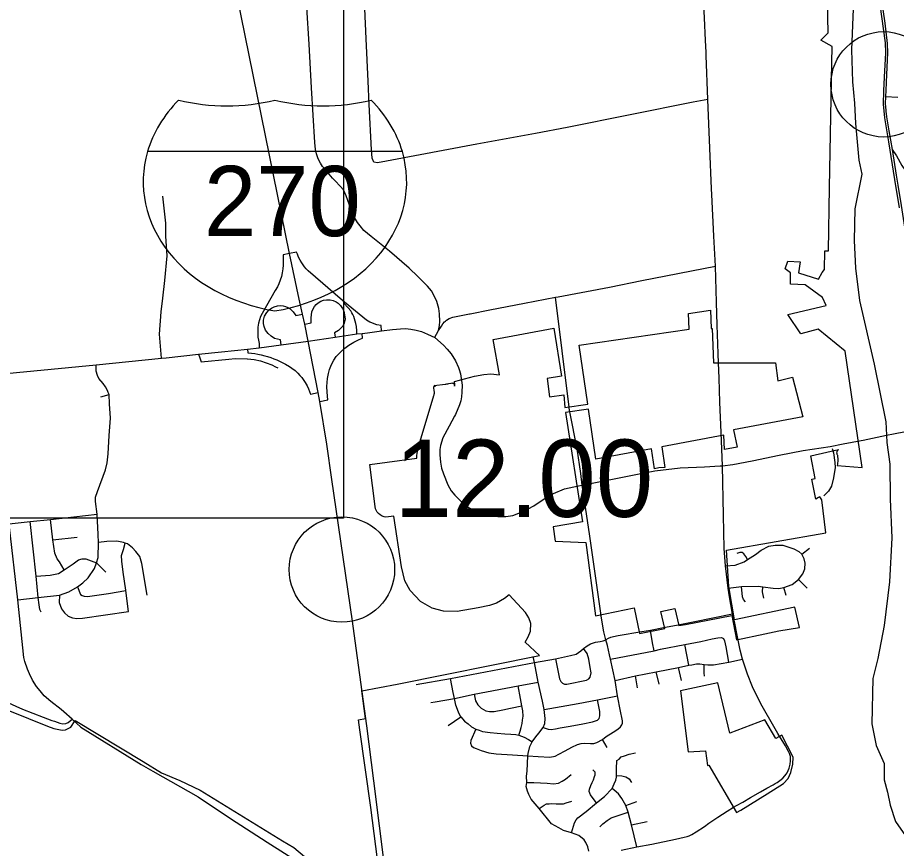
# Model space of a CAD drawing. Extents: x 1659811 to 1934326, y 644115 to 934867.
# Drawn here: x 1789672 to 1802180, y 733916 to 745742 of the extents above; entities that cross this region are included whole.
import ezdxf

# ---------------------------------------------------------------- set-up
doc = ezdxf.new("R2010")
doc.units = 0
for name, color, linetype in [('Default', 7, 'Continuous'), ('GM_X_City_Street', 7, 'Continuous'), ('GM_X_Corporation', 7, 'Continuous'), ('GM_X_County_Road', 7, 'Continuous'), ('GM_X_Interchange_Ramps', 7, 'Continuous'), ('GM_X_Interstate_Route', 7, 'Continuous'), ('GM_X_Interstate_Shield', 7, 'Continuous'), ('GM_X_Township', 7, 'Continuous'), ('GM_X_Township_Road', 7, 'Continuous'), ('GM_X_US_Route', 7, 'Continuous'), ('SC_Scratch1', 7, 'Continuous')]:
    doc.layers.add(name, color=color, linetype=linetype)

msp = doc.modelspace()

# ---------------------------------------------------------------- linework, layer by layer
at = {"layer": 'Default'}
for centre in [(1801998, 744792), (1794288, 737885)]:
    msp.add_circle(centre, 750, dxfattribs=at)
at = {"layer": 'GM_X_City_Street'}
for points in [[(1795663, 741290), (1795678, 741361), (1795683, 741414), (1795679, 741527), (1795668, 741602), (1795639, 741699), (1795602, 741783), (1795561, 741853), (1795507, 741919), (1795370, 742058), (1795243, 742175), (1794967, 742417), (1794706, 742627), (1794600, 742710), (1794548, 742777), (1794511, 742823), (1794469, 742896), (1794397, 743073), (1794350, 743203), (1794310, 743288), (1794261, 743343), (1794192, 743419), (1794155, 743455), (1794083, 743543), (1794013, 743621), (1793984, 743671), (1793952, 743733), (1793927, 743805), (1793912, 743865), (1793901, 743964), (1793856, 744742), (1793822, 745363), (1793790, 745884)], [(1799549, 743305), (1799525, 743884), (1799496, 744577), (1799472, 745204), (1799470, 745250)], [(1802022, 744618), (1802202, 744611)], [(1799496, 744577), (1799289, 744537)], [(1802119, 743863), (1802179, 743775), (1802258, 743638), (1802335, 743526), (1802389, 743466), (1802417, 743438), (1802451, 743403), (1802563, 743352), (1802790, 743282), (1802918, 743227)], [(1791719, 740894), (1791693, 741238), (1791715, 741554), (1791737, 741750), (1791769, 742000), (1791802, 742349), (1791780, 742632), (1791780, 742818), (1791737, 743199)], [(1795616, 741203), (1795636, 741236), (1795663, 741290), (1795705, 741352), (1795726, 741382), (1795748, 741410), (1795761, 741423)], [(1792575, 740984), (1792943, 741023), (1793111, 741042), (1793423, 741084), (1793807, 741137), (1794194, 741191), (1794500, 741239), (1794577, 741246), (1794650, 741255), (1794852, 741283), (1795006, 741303), (1795067, 741309), (1795123, 741314), (1795192, 741315), (1795267, 741308), (1795345, 741293), (1795422, 741272), (1795505, 741238), (1795608, 741189), (1795616, 741203)], [(1795608, 741189), (1795735, 741080), (1795787, 741024), (1795844, 740955), (1795905, 740857), (1795947, 740763), (1795955, 740734)], [(1791786, 740901), (1792249, 740949), (1792575, 740984)], [(1799686, 739836), (1799686, 739837), (1799668, 740268), (1799655, 740610), (1799648, 740830), (1799643, 740956), (1799637, 741097)], [(1785644, 740199), (1786132, 740262), (1786526, 740311), (1786898, 740356), (1787185, 740392), (1787465, 740426), (1788258, 740523), (1789260, 740650), (1790792, 740800), (1791719, 740894), (1791786, 740901)], [(1792249, 740949), (1792266, 740900), (1792287, 740842), (1792680, 740880), (1792769, 740889), (1792938, 740884)], [(1792938, 740884), (1792945, 740884), (1793040, 740874), (1793130, 740856), (1793290, 740797), (1793344, 740773), (1793376, 740755)], [(1789673, 737452), (1789966, 737487), (1790268, 737519), (1790402, 737566), (1790524, 737637), (1790600, 737694), (1790675, 737769), (1790766, 737899), (1790797, 737979), (1790821, 738059), (1790823, 738271), (1790819, 738382), (1790805, 738673), (1790781, 738852), (1790783, 738914), (1790811, 738998), (1790921, 739307), (1790947, 739405), (1790960, 739531), (1790977, 739792), (1790992, 740041), (1790981, 740243), (1790973, 740376), (1790962, 740406), (1790952, 740434), (1790924, 740487), (1790891, 740533), (1790830, 740607), (1790808, 740647), (1790790, 740710), (1790792, 740800)], [(1795955, 740734), (1795974, 740669), (1795997, 740511), (1795995, 740409), (1795989, 740343), (1795979, 740286), (1795963, 740232), (1795903, 740091), (1795892, 740070)], [(1790330, 735859), (1790292, 735892), (1790145, 736005), (1790050, 736089), (1789991, 736157), (1789940, 736221), (1789885, 736311), (1789842, 736402), (1789813, 736469), (1789773, 736577), (1789761, 736632), (1789673, 737452), (1789559, 738488), (1789553, 738537), (1789407, 739533), (1789344, 740018), (1789285, 740516), (1789260, 740650)], [(1790856, 740345), (1790973, 740376)], [(1797523, 740183), (1797520, 740200), (1797516, 740235)], [(1795892, 740070), (1795814, 739927), (1795724, 739761), (1795689, 739652), (1795682, 739594), (1795682, 739520), (1795691, 739416), (1795707, 739330), (1795733, 739250), (1795796, 739091), (1795843, 739007), (1795893, 738943), (1795951, 738888), (1796013, 738827), (1796101, 738765), (1796186, 738727), (1796328, 738676), (1796450, 738646), (1796505, 738641), (1796619, 738639), (1796722, 738657), (1796784, 738678), (1796916, 738736), (1796940, 738750)], [(1802139, 739816), (1802652, 739919)], [(1801677, 739723), (1801706, 739729), (1802039, 739796), (1802137, 739815), (1802139, 739816)], [(1801264, 739609), (1801286, 739547), (1801303, 739411), (1801309, 739337), (1801286, 739190), (1801258, 739072), (1801212, 739000), (1801146, 738935)], [(1783677, 739468), (1783922, 739315), (1784567, 738918), (1785211, 738522), (1786306, 737848), (1786531, 737713), (1787324, 737219), (1787916, 736848), (1788483, 736500), (1788730, 736352), (1788792, 736319), (1789122, 736169), (1789347, 736074), (1789742, 735899), (1790034, 735782), (1790159, 735738)], [(1796940, 738750), (1797017, 738793), (1797153, 738883), (1797265, 738949), (1797300, 738970), (1797458, 739032), (1797655, 739076), (1797706, 739086)], [(1789553, 738537), (1789852, 738568), (1790142, 738600), (1790805, 738673)], [(1790006, 737278), (1789990, 737318), (1789978, 737381), (1789966, 737487), (1789935, 737792), (1789852, 738568)], [(1790337, 737879), (1790270, 737993), (1790234, 738039), (1790201, 738117), (1790175, 738306), (1790142, 738600)], [(1790175, 738306), (1790522, 738348)], [(1791517, 737523), (1791441, 737970), (1791411, 738069), (1791353, 738143), (1791306, 738194), (1791238, 738250), (1791202, 738263), (1791180, 738270), (1791086, 738289), (1790940, 738283), (1790823, 738271)], [(1791252, 737289), (1791214, 737585), (1791213, 737592), (1791174, 737847), (1791157, 738004), (1791153, 738086), (1791178, 738170), (1791202, 738263)], [(1799747, 737936), (1799887, 737946), (1800011, 737994), (1800061, 738029), (1800172, 738101), (1800255, 738162), (1800366, 738216), (1800452, 738233), (1800563, 738231), (1800636, 738210), (1800722, 738178), (1800792, 738141), (1800833, 738105)], [(1799783, 737618), (1799973, 737646), (1800212, 737649), (1800280, 737640), (1800426, 737618), (1800508, 737615), (1800577, 737632), (1800694, 737673), (1800787, 737744), (1800849, 737826), (1800875, 737895), (1800881, 737978), (1800866, 738039), (1800833, 738105)], [(1800061, 738029), (1800035, 738072), (1800009, 738108), (1799982, 738127), (1799949, 738128), (1799910, 738112)], [(1800833, 738105), (1800943, 738188)], [(1789935, 737792), (1790134, 737806), (1790252, 737828), (1790337, 737879), (1790461, 737966), (1790539, 738023), (1790593, 738039), (1790644, 738040), (1790797, 737979)], [(1790797, 737979), (1790930, 737850)], [(1800787, 737744), (1800911, 737622)], [(1790524, 737637), (1790565, 737530), (1790593, 737514), (1790621, 737506), (1790669, 737504), (1790967, 737543), (1791214, 737585)], [(1800031, 737424), (1800004, 737458), (1799991, 737499), (1799973, 737646)], [(1800295, 737478), (1800274, 737569), (1800280, 737640)], [(1800612, 737516), (1800577, 737632)], [(1790268, 737519), (1790264, 737417), (1790298, 737325), (1790338, 737269), (1790394, 737224), (1790455, 737200), (1790517, 737190), (1790595, 737193), (1791252, 737289)], [(1798045, 736887), (1798016, 736998), (1797975, 737251)], [(1798557, 736998), (1798218, 736940), (1798110, 736918), (1798075, 736905), (1798045, 736887)], [(1798733, 736729), (1798709, 736844), (1798679, 737019)], [(1799073, 737095), (1799048, 737091), (1798867, 737055)], [(1797031, 736564), (1797328, 736616), (1797540, 736660), (1797624, 736681), (1797687, 736727), (1797724, 736760), (1797778, 736801), (1797827, 736830), (1797895, 736851), (1797962, 736862), (1798006, 736873), (1798045, 736887)], [(1798252, 735645), (1798270, 735675), (1798279, 735699), (1798282, 735732), (1798277, 735755), (1798254, 735869), (1798211, 736086), (1798177, 736306), (1798112, 736612), (1798095, 736673), (1798069, 736806), (1798045, 736887)], [(1798112, 736612), (1798733, 736729), (1798823, 736751), (1799170, 736818), (1799398, 736861), (1799557, 736899), (1799638, 736911), (1799690, 736917), (1799717, 736902)], [(1799795, 736566), (1799758, 736787), (1799748, 736827), (1799740, 736870), (1799717, 736902)], [(1800494, 735551), (1800455, 735618), (1800249, 735973), (1800132, 736217), (1800061, 736396), (1799991, 736610), (1799957, 736739), (1799918, 736926), (1799912, 736953)], [(1797328, 736616), (1797362, 736447), (1797383, 736332), (1797403, 736292), (1797425, 736269), (1797454, 736253), (1797487, 736252), (1797770, 736310), (1797803, 736329), (1797823, 736353), (1797836, 736414), (1797823, 736489), (1797803, 736611), (1797777, 736689), (1797724, 736760)], [(1799227, 736523), (1799170, 736818)], [(1797802, 733878), (1797787, 733940), (1797761, 733998), (1797737, 734036), (1797662, 734099), (1797556, 734140), (1797441, 734173), (1797373, 734207), (1797273, 734267), (1797093, 734482), (1796983, 734618), (1796950, 734682), (1796927, 734733), (1796909, 734795), (1796920, 734854), (1796916, 734942), (1796925, 735014), (1796936, 735234), (1796937, 735265), (1796962, 735366), (1796997, 735432), (1797048, 735506), (1797092, 735556), (1797150, 735638), (1797175, 735693), (1797181, 735767), (1797167, 735892), (1797142, 736010), (1797081, 736283), (1797031, 736564), (1797012, 736647)], [(1798177, 736306), (1798467, 736374), (1798762, 736430), (1799076, 736493), (1799227, 736523), (1799266, 736531), (1799333, 736545), (1799383, 736543), (1799445, 736533), (1799495, 736527), (1799576, 736529), (1799795, 736566), (1799991, 736610)], [(1795345, 736249), (1795832, 736336), (1797031, 736564)], [(1799121, 736304), (1799076, 736493)], [(1799448, 736367), (1799445, 736414), (1799445, 736533)], [(1798495, 736200), (1798467, 736374)], [(1798801, 736256), (1798762, 736430)], [(1795614, 736004), (1795891, 736051), (1796170, 736110), (1796795, 736230), (1797081, 736283)], [(1795982, 735790), (1795952, 735840), (1795931, 735892), (1795908, 735957), (1795891, 736051), (1795873, 736137), (1795832, 736336)], [(1796805, 735529), (1796825, 735586), (1796837, 735635), (1796851, 735693), (1796857, 735743), (1796868, 735800), (1796865, 735873), (1796850, 735945), (1796828, 736051), (1796795, 736230)], [(1796170, 736110), (1796190, 736016), (1796221, 735958), (1796269, 735911), (1796337, 735874), (1796386, 735863), (1796454, 735866), (1796578, 735889), (1796688, 735914), (1796850, 735945)], [(1795553, 735993), (1795614, 736004)], [(1797150, 735638), (1797224, 735613), (1797267, 735610), (1797326, 735616), (1797394, 735631), (1797537, 735656), (1797719, 735690), (1797852, 735718), (1797898, 735733), (1797926, 735743), (1797948, 735764), (1797957, 735804), (1797960, 735863), (1797926, 736030)], [(1797167, 735892), (1797648, 735978), (1797926, 736030), (1798211, 736086)], [(1790451, 735756), (1790330, 735859)], [(1790159, 735738), (1790195, 735725), (1790275, 735697), (1790316, 735691), (1790357, 735696), (1790391, 735708), (1790451, 735756)], [(1790451, 735756), (1790572, 735640), (1791432, 735108), (1791596, 735016)], [(1795802, 735665), (1795982, 735790)], [(1795982, 735790), (1796033, 735729), (1796084, 735688), (1796132, 735648), (1796195, 735615), (1796239, 735597), (1796291, 735582), (1796398, 735566), (1796497, 735556), (1796607, 735548), (1796691, 735544), (1796762, 735536), (1796805, 735529), (1796884, 735500), (1796944, 735467), (1796997, 735432)], [(1796195, 735615), (1796122, 735450), (1796117, 735412), (1796132, 735374), (1796162, 735353), (1796198, 735336), (1796271, 735308), (1796380, 735275), (1796482, 735262), (1796715, 735247), (1796936, 735234), (1797079, 735226), (1797249, 735216), (1797323, 735229), (1797376, 735256), (1797465, 735305), (1797558, 735355), (1797640, 735396), (1797695, 735411), (1797747, 735414), (1797825, 735407), (1797873, 735407), (1797917, 735422), (1797995, 735467), (1798050, 735508), (1798150, 735571), (1798216, 735615), (1798252, 735645)], [(1798064, 735353), (1797995, 735467)], [(1798201, 735166), (1798234, 735188), (1798264, 735218), (1798310, 735234), (1798376, 735257), (1798468, 735276)], [(1797556, 734140), (1797598, 734279), (1797622, 734323), (1797646, 734352), (1797764, 734443), (1797911, 734567), (1798027, 734653), (1798132, 734771), (1798163, 734833), (1798188, 734885), (1798196, 734929), (1798196, 734955), (1798197, 734975), (1798198, 735031), (1798196, 735091), (1798201, 735125), (1798201, 735166)], [(1791596, 735016), (1792240, 734652), (1792700, 734340), (1793224, 734005), (1793962, 733534), (1794593, 733184), (1794983, 732956), (1795071, 732926), (1795122, 732913), (1795164, 732910)], [(1797911, 734567), (1797849, 734644), (1797824, 734678), (1797806, 734727), (1797811, 734759), (1797832, 734811), (1797848, 734853), (1797867, 734893), (1797884, 734941), (1797890, 734963), (1797890, 734999), (1797861, 735034)], [(1796920, 734854), (1797020, 734853), (1797210, 734846), (1797298, 734833), (1797372, 734846), (1797423, 734873), (1797471, 734901), (1797551, 734969)], [(1798196, 734955), (1798272, 734949), (1798328, 734934), (1798374, 734904), (1798409, 734852)], [(1798483, 733938), (1798411, 734250), (1798362, 734434), (1798329, 734525), (1798273, 734625), (1798222, 734694), (1798164, 734743), (1798132, 734771)], [(1797093, 734482), (1797164, 734531), (1797201, 734549), (1797237, 734552), (1797275, 734556), (1797337, 734549), (1797393, 734550), (1797441, 734551), (1797478, 734567), (1797558, 734588)], [(1798262, 733893), (1798483, 733938), (1798701, 733975), (1799035, 734046), (1799160, 734074), (1799202, 734087), (1799231, 734097), (1799268, 734116), (1799328, 734150), (1799447, 734228), (1799512, 734275), (1799581, 734322), (1799639, 734362), (1799771, 734446), (1799859, 734501), (1799906, 734528)], [(1798329, 734525), (1798486, 734584)], [(1797960, 734224), (1798003, 734267), (1798061, 734313), (1798119, 734350), (1798362, 734434)], [(1798411, 734250), (1798634, 734300)]]:
    msp.add_lwpolyline(points, dxfattribs=at)
at = {"layer": 'GM_X_Corporation'}
for points in [[(1794861, 733242), (1794699, 734497), (1794545, 735602), (1794525, 735745), (1794624, 735763), (1794570, 736161), (1795072, 736254), (1797098, 736664), (1796898, 736851), (1796940, 736926), (1796970, 737010), (1796975, 737119), (1796947, 737199), (1796900, 737273), (1796669, 737527), (1796601, 737474), (1796487, 737408), (1796389, 737373), (1796226, 737341), (1795929, 737286), (1795732, 737292), (1795571, 737335), (1795407, 737432), (1795257, 737587), (1795185, 737723), (1795137, 737924), (1795029, 738645), (1794951, 738634), (1794915, 738633), (1794889, 738637), (1794863, 738646), (1794833, 738663), (1794810, 738682), (1794791, 738704), (1794776, 738730), (1794767, 738751), (1794761, 738782), (1794687, 739379), (1794932, 739413), (1795353, 739472), (1795356, 739509), (1795364, 739564), (1795371, 739604), (1795380, 739643), (1795389, 739677), (1795400, 739714), (1795598, 740361), (1795600, 740370), (1795602, 740377), (1795603, 740384), (1795604, 740394), (1795605, 740401), (1795605, 740409), (1795604, 740415), (1795603, 740425), (1795596, 740483), (1795595, 740488), (1795593, 740491), (1795622, 740496), (1795614, 740501), (1795603, 740504), (1795756, 740523), (1795769, 740526), (1795782, 740529), (1795795, 740531), (1795811, 740534), (1795843, 740540), (1795853, 740541), (1795862, 740540), (1795869, 740537), (1795876, 740533), (1795883, 740527), (1795887, 740521), (1795889, 740516), (1795892, 740494), (1795895, 740520), (1795894, 740530), (1795892, 740542), (1795888, 740563), (1796176, 740637), (1796307, 740663), (1796408, 740671), (1796532, 740659), (1796442, 741158), (1797302, 741323), (1797412, 740638), (1797207, 740606), (1797242, 740342), (1797444, 740374), (1797459, 740191), (1797786, 740238), (1797664, 741078), (1799228, 741305), (1799220, 741530), (1799534, 741576), (1799542, 741316), (1799558, 741318), (1799575, 740830), (1800457, 740830), (1800493, 740571), (1800699, 740622), (1800850, 740057), (1799860, 739872), (1799911, 739627), (1799731, 739593), (1799723, 739796), (1798839, 739630), (1798886, 739338), (1798799, 739334), (1798737, 739318), (1798692, 739605), (1797903, 739457), (1797796, 740170), (1797469, 740123), (1797713, 738565), (1797296, 738495), (1797323, 738291), (1797759, 738271), (1797898, 737226), (1798449, 737341), (1798524, 736975), (1798882, 737045), (1798827, 737288), (1799026, 737330), (1799082, 737088), (1799179, 737105), (1799836, 737231), (1799906, 736887), (1800305, 736970), (1800508, 737011), (1800801, 737062), (1800735, 737351), (1799874, 737168), (1799795, 737644), (1799761, 738159), (1801173, 738406), (1801119, 738880), (1801089, 738921), (1801071, 738909), (1801032, 738885), (1800975, 739174), (1801024, 739183), (1800963, 739506), (1801356, 739592), (1801351, 739589), (1801346, 739585), (1801343, 739582), (1801339, 739577), (1801335, 739571), (1801333, 739567), (1801331, 739562), (1801330, 739557), (1801329, 739549), (1801329, 739546), (1801330, 739540), (1801331, 739535), (1801332, 739530), (1801335, 739524), (1801342, 739514), (1801343, 739495), (1801345, 739462), (1801344, 739422), (1801342, 739404), (1801341, 739386), (1801338, 739365), (1801694, 739338), (1801449, 740993), (1801066, 741306), (1800821, 741241), (1800636, 741516), (1801179, 741642), (1801130, 741758), (1800882, 741940), (1800674, 741946), (1800674, 742111), (1800596, 742166), (1800636, 742276), (1800810, 742267), (1800786, 742107), (1801071, 742020), (1801125, 742113), (1801155, 742156), (1801160, 742422), (1801214, 742421), (1801229, 743323), (1801259, 745100), (1801263, 745329), (1801105, 745419), (1801209, 745526), (1801161, 747779)], [(1801946, 745930), (1802019, 745382), (1802026, 745240), (1802006, 744894), (1801995, 744699), (1801990, 744508), (1802010, 744316), (1802068, 743972), (1802151, 743437), (1802219, 743032)], [(1789012, 736092), (1790098, 735655), (1790189, 735623), (1790305, 735599), (1790352, 735602), (1790432, 735643), (1790492, 735739), (1791458, 735151), (1791718, 734992), (1791982, 734884), (1792270, 734745), (1793442, 734023), (1793602, 733927), (1793997, 733597)]]:
    msp.add_lwpolyline(points, dxfattribs=at)
msp.add_lwpolyline([(1799215, 735290), (1799463, 735307), (1799493, 735096), (1799508, 735100), (1799905, 734427), (1799964, 734461), (1800338, 734694), (1800572, 734842), (1800640, 734911), (1800676, 734997), (1800706, 735114), (1800712, 735217), (1800549, 735530), (1800463, 735480), (1800309, 735744), (1799811, 735556), (1799640, 736275), (1799108, 736159)], close=True, dxfattribs=at)
at = {"layer": 'GM_X_County_Road'}
for points in [[(1799470, 745250), (1799463, 745414), (1799449, 745737), (1799441, 745913), (1799393, 746138), (1799379, 746190), (1799202, 746813), (1799165, 746949)], [(1799637, 741097), (1799627, 741366), (1799618, 741691), (1799603, 742203), (1799579, 742632), (1799552, 743225), (1799549, 743305)], [(1797364, 741767), (1798098, 741907), (1798557, 741999), (1799603, 742203)], [(1796113, 741527), (1796394, 741580), (1796886, 741676), (1797329, 741761), (1797364, 741767)], [(1797516, 740235), (1797329, 741761)], [(1795761, 741423), (1795775, 741437), (1795813, 741458), (1795866, 741479), (1796106, 741525), (1796113, 741527)], [(1797975, 737251), (1797973, 737264), (1797810, 738392), (1797706, 739086), (1797689, 739251), (1797637, 739603), (1797532, 740130), (1797523, 740183)], [(1799703, 739362), (1799686, 739836)], [(1799670, 739360), (1799703, 739362), (1799850, 739382), (1800126, 739432), (1800512, 739513), (1800852, 739578), (1801237, 739639), (1801420, 739674)], [(1801420, 739674), (1801677, 739723)], [(1797706, 739086), (1798496, 739242), (1798740, 739291), (1799100, 739335), (1799450, 739346), (1799670, 739360)], [(1799912, 736953), (1799878, 737120), (1799846, 737251), (1799802, 737499), (1799783, 737618), (1799747, 737936), (1799728, 738186), (1799717, 738661), (1799703, 739362)], [(1800456, 734839), (1800482, 734854), (1800522, 734882), (1800563, 734915), (1800593, 734947), (1800610, 734972), (1800624, 734993), (1800655, 735059), (1800669, 735113), (1800674, 735162), (1800674, 735194), (1800671, 735225), (1800658, 735266), (1800642, 735297), (1800600, 735374), (1800494, 735551)], [(1799906, 734528), (1799992, 734576), (1800104, 734642), (1800244, 734721), (1800336, 734772), (1800425, 734821), (1800456, 734839)]]:
    msp.add_lwpolyline(points, dxfattribs=at)
at = {"layer": 'GM_X_Interchange_Ramps'}
for points in [[(1793541, 742384), (1793451, 742366), (1793453, 742283), (1793452, 742216), (1793448, 742168), (1793438, 742109), (1793426, 742058), (1793410, 742006), (1793388, 741950), (1793370, 741911), (1793340, 741857), (1793152, 741532), (1793131, 741486), (1793115, 741441), (1793102, 741390), (1793093, 741336), (1793089, 741293), (1793089, 741240), (1793093, 741191), (1793100, 741151), (1793108, 741104), (1793111, 741042)], [(1794852, 741283), (1794845, 741357), (1794784, 741371), (1794746, 741383), (1794715, 741395), (1794686, 741408), (1794663, 741420), (1794636, 741436), (1794323, 741691), (1794295, 741714), (1793808, 742135), (1793780, 742165), (1793757, 742193), (1793735, 742223), (1793717, 742249), (1793693, 742290), (1793671, 742333), (1793654, 742374), (1793643, 742404), (1793541, 742384)], [(1793423, 741084), (1793415, 741154), (1793369, 741163), (1793326, 741176), (1793281, 741207), (1793236, 741244), (1793198, 741295), (1793179, 741344), (1793172, 741388), (1793173, 741434), (1793188, 741491), (1793217, 741544), (1793252, 741583), (1793286, 741607), (1793323, 741625), (1793370, 741638), (1793415, 741642), (1793451, 741638), (1793486, 741629), (1793516, 741616), (1793549, 741596), (1793574, 741575), (1793595, 741552), (1793631, 741501), (1793727, 741520)], [(1793758, 741379), (1793852, 741398), (1793850, 741470), (1793861, 741553), (1793878, 741598), (1793899, 741631), (1793920, 741656), (1793952, 741683), (1793989, 741704), (1794026, 741718), (1794068, 741725), (1794120, 741724), (1794165, 741714), (1794205, 741695), (1794234, 741676), (1794270, 741642), (1794297, 741602), (1794313, 741564), (1794325, 741511), (1794334, 741451), (1794322, 741393), (1794300, 741349), (1794274, 741321), (1794237, 741287), (1794181, 741254), (1794194, 741191)], [(1794500, 741239), (1794501, 741285), (1794495, 741343), (1794487, 741387), (1794478, 741422), (1794469, 741452), (1794457, 741485), (1794443, 741517), (1794430, 741540), (1794413, 741569), (1794377, 741610), (1794313, 741679), (1794323, 741691)], [(1793974, 740278), (1794087, 740299), (1794079, 740412), (1794073, 740493), (1794081, 740605), (1794095, 740677), (1794112, 740734), (1794141, 740805), (1794173, 740866), (1794207, 740919), (1794288, 741000), (1794328, 741036), (1794385, 741078), (1794457, 741124), (1794532, 741160), (1794583, 741179), (1794577, 741246)], [(1792943, 741023), (1792949, 740970), (1793003, 740965), (1793048, 740959), (1793091, 740952), (1793140, 740941), (1793193, 740928), (1793230, 740917), (1793277, 740902), (1793321, 740885), (1793360, 740869), (1793399, 740851), (1793487, 740807), (1793541, 740776), (1793575, 740753), (1793622, 740717), (1793660, 740682), (1793691, 740649), (1793715, 740621), (1793738, 740591), (1793767, 740547), (1793794, 740499), (1793814, 740456), (1793842, 740383), (1793952, 740404)]]:
    msp.add_lwpolyline(points, dxfattribs=at)
at = {"layer": 'GM_X_Interstate_Route'}
for points in [[(1793680, 741736), (1793541, 742384), (1792510, 747451), (1792028, 749783)], [(1794145, 739169), (1794072, 739672), (1793974, 740278), (1793952, 740404), (1793807, 741137), (1793758, 741379), (1793727, 741520), (1793680, 741736)], [(1794438, 737151), (1794145, 739169)], [(1794740, 734878), (1794642, 735660), (1794478, 736870), (1794438, 737151)], [(1795311, 729935), (1795293, 730422), (1795244, 730841), (1795239, 730931), (1795097, 731981), (1794983, 732956), (1794740, 734878)]]:
    msp.add_lwpolyline(points, dxfattribs=at)
at = {"layer": 'GM_X_Interstate_Shield'}
msp.add_line((1795148, 743834), (1791522, 743834), dxfattribs=at)
msp.add_line((1795148, 743834), (1791522, 743834), dxfattribs=at)
for centre, start_param, end_param in [((1793803, 743405), 2.47259, 2.911027), ((1792650, 746361), 4.415841, 5.008937), ((1794020, 746361), 4.415841, 5.008937), ((1792866, 743405), 0.230566, 0.669003), ((1793803, 743405), 2.911027, 4.511031), ((1792866, 743405), 4.913747, 6.513751)]:
    msp.add_ellipse(centre, major_axis=(2344, 0), ratio=0.8, start_param=start_param, end_param=end_param, dxfattribs=at)
at = {"layer": 'GM_X_Township'}
msp.add_lwpolyline([(1801562, 745866), (1801541, 745281), (1801555, 744826), (1801583, 744523), (1801596, 744234), (1801645, 743711), (1801686, 743511), (1801590, 743022), (1801576, 742568), (1801596, 742175), (1801652, 741717), (1801865, 740808), (1802030, 739989), (1802039, 739796), (1802044, 739693), (1802085, 739383), (1802092, 738887), (1802113, 738337), (1802079, 737710), (1802003, 737090), (1801913, 736619), (1801845, 736336), (1801831, 735689), (1801893, 735379), (1802003, 735125), (1802003, 734890), (1802051, 734718), (1802093, 734532), (1802168, 734298), (1802485, 733844)], dxfattribs=at)
at = {"layer": 'GM_X_Township_Road'}
for points in [[(1794661, 744839), (1794633, 745438), (1794613, 745872), (1794601, 745937), (1794581, 745999), (1794568, 746042)], [(1799289, 744537), (1799289, 744537), (1797495, 744179), (1797042, 744094), (1796208, 743940), (1794921, 743699), (1794796, 743673), (1794744, 743685), (1794716, 743741), (1794710, 743860), (1794677, 744507), (1794661, 744839)], [(1799846, 737251), (1799288, 737135), (1799073, 737095)], [(1798867, 737055), (1798679, 737019), (1798557, 736998)]]:
    msp.add_lwpolyline(points, dxfattribs=at)
at = {"layer": 'GM_X_US_Route'}
for points in [[(1801908, 746436), (1801953, 746090), (1802014, 745664), (1802048, 745374), (1802055, 745242), (1802039, 744933), (1802027, 744702), (1802022, 744618), (1802020, 744514), (1802027, 744425), (1802029, 744408)], [(1802029, 744408), (1802039, 744329), (1802070, 744131), (1802119, 743863), (1802174, 743498), (1802200, 743355), (1802246, 743066), (1802325, 742572), (1802378, 742283), (1802405, 742099), (1802458, 741733), (1802511, 741386), (1802540, 741172), (1802610, 740699), (1802654, 740359), (1802716, 739932)]]:
    msp.add_lwpolyline(points, dxfattribs=at)
at = {"layer": 'SC_Scratch1'}
msp.add_lwpolyline([(1659811, 738617), (1659811, 934867), (1794311, 934867), (1794311, 738617)], close=True, dxfattribs=at)

# ---------------------------------------------------------------- texts
at = {"layer": 'Default'}
msp.add_text('12.00', height=1100, dxfattribs=at).set_placement((1795038, 738635))
at = {"layer": 'GM_X_Interstate_Shield'}
msp.add_text('270', height=1000, dxfattribs=at).set_placement((1792325, 742631))

doc.saveas('drawing.dxf')
